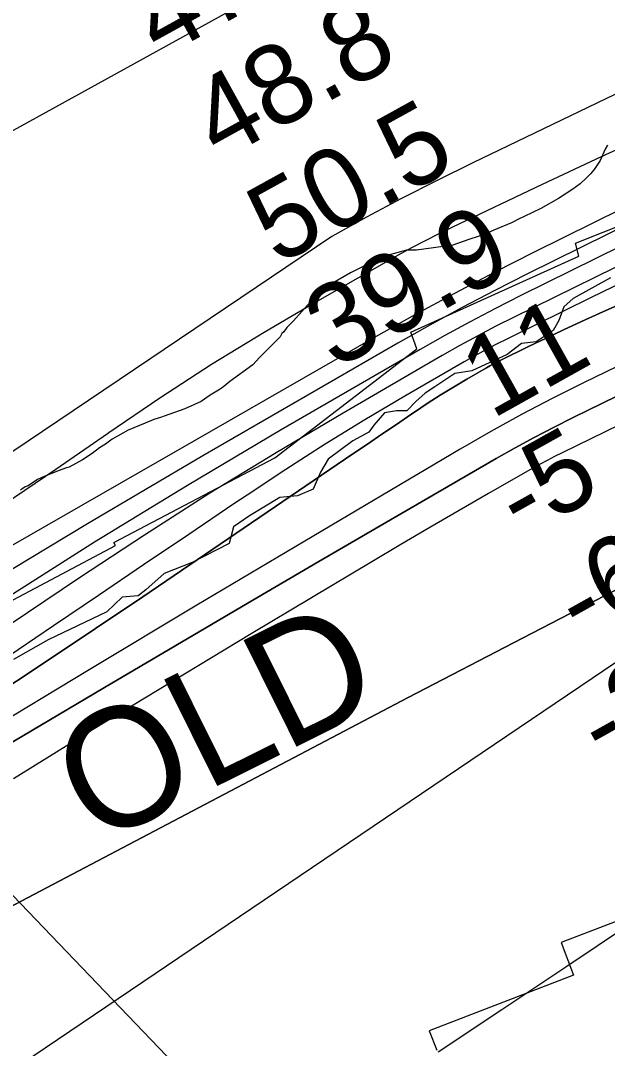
# Model space of a CAD drawing. Extents: x 3177385 to 3215275, y 903885 to 929304.
# Drawn here: x 3183725 to 3184218, y 910634 to 911498 of the extents above; entities that cross this region are included whole.
import ezdxf

# ---------------------------------------------------------------- set-up
doc = ezdxf.new("R2010")
doc.units = 0
for name, color, linetype in [('V-RIVR-EDGE', 7, 'Continuous'), ('V-RIVR-RANG', 7, 'Continuous'), ('V-RRAP-RVMT', 7, 'Continuous'), ('V-RRAP-RVMT-IDEN', 7, 'Continuous'), ('V-SITE-VEGE', 7, 'Continuous'), ('V-TOPO-DPTH', 7, 'Continuous'), ('V-TOPO-MAJR', 7, 'Continuous'), ('V-TOPO-MINR', 7, 'Continuous'), ('V-TOPO-WATR', 7, 'Continuous')]:
    doc.layers.add(name, color=color, linetype=linetype)

msp = doc.modelspace()

# ---------------------------------------------------------------- linework, layer by layer
at = {"layer": 'V-RIVR-EDGE'}
for points in [[(3184221.07, 911282.08), (3184189.62, 911264.61), (3184181.75, 911257.7), (3184177.56, 911246.17), (3184172.92, 911237.86), (3184158.58, 911228.2), (3184146.11, 911226.84), (3184134.08, 911217.64), (3184104.48, 911203.85), (3184090.16, 911201.58)], [(3184090.16, 911201.58), (3184073.5, 911190.54), (3184065.18, 911185.01), (3184057.31, 911178.11), (3184049.9, 911170.27), (3184041.12, 911170.29), (3184030.96, 911168.47), (3184022.16, 911158.33), (3184017.98, 911152.34), (3184004.57, 911144.98), (3183983.75, 911129.79), (3183977.26, 911118.72), (3183971.22, 911104.42), (3183957.81, 911098.91), (3183943.03, 911097.56), (3183917.58, 911081.92), (3183904.17, 911072.72), (3183900.44, 911058.87), (3183869.45, 911042.78), (3183845.87, 911033.6), (3183830.6, 911019.78), (3183824.12, 911014.72), (3183810.72, 911013.83), (3183797.76, 911001.39), (3183748.28, 910977.95), (3183719.14, 910961.4)]]:
    msp.add_lwpolyline(points, dxfattribs=at)
at = {"layer": 'V-RIVR-RANG'}
msp.add_line((3183274.2, 911225.62), (3183980.74, 910489.96), dxfattribs=at)
at = {"layer": 'V-RRAP-RVMT'}
for p, q in [((3184191.63, 911311.06), (3184332.05, 911367.55)), ((3184194.49, 911300.27), (3184191.63, 911311.06)), ((3184053.26, 911236.45), (3184194.49, 911300.27)), ((3184058.23, 911222.29), (3184053.26, 911236.45)), ((3183939.02, 911130.92), (3184058.23, 911222.29)), ((3183803.6, 911059.75), (3183939.02, 911130.92)), ((3183805.07, 911057.02), (3183803.6, 911059.75)), ((3183674.33, 910987.92), (3183805.07, 911057.02)), ((3184300.8, 910770.14), (3184179.43, 910723.56)), ((3184179.43, 910723.56), (3184190.03, 910695.96)), ((3184190.03, 910695.96), (3184068.66, 910649.37)), ((3184068.66, 910649.37), (3184074.96, 910632.97))]:
    msp.add_line(p, q, dxfattribs=at)
at = {"layer": 'V-SITE-VEGE'}
for p, q in [((3184216.41, 911390.06), (3184212.37, 911380.79)), ((3184218.44, 911393.66), (3184216.41, 911390.06)), ((3184212.37, 911380.79), (3184207.29, 911373.05)), ((3184204.23, 911369.43), (3184200.66, 911365.82)), ((3184207.29, 911373.05), (3184204.23, 911369.43)), ((3184195.56, 911361.16), (3184189.44, 911356.49)), ((3184200.66, 911365.82), (3184195.56, 911361.16)), ((3184189.44, 911356.49), (3184177.17, 911348.71)), ((3184177.17, 911348.71), (3184162.34, 911340.39)), ((3184162.34, 911340.39), (3184148.52, 911333.62)), ((3184137.78, 911328.41), (3184122.93, 911322.15)), ((3184144.94, 911332.05), (3184137.78, 911328.41)), ((3184148.52, 911333.62), (3184144.94, 911332.05)), ((3184119.86, 911320.58), (3184110.65, 911316.93)), ((3184122.93, 911322.15), (3184119.86, 911320.58)), ((3184088.63, 911309.58), (3184057.85, 911305.26)), ((3184101.94, 911314.3), (3184088.63, 911309.58)), ((3184110.65, 911316.93), (3184101.94, 911314.3)), ((3184035.29, 911301.51), (3184025.05, 911297.84)), ((3184049.64, 911305.2), (3184035.29, 911301.51)), ((3184057.85, 911305.26), (3184049.64, 911305.2)), ((3184025.05, 911297.84), (3184002.54, 911286.39)), ((3184002.54, 911286.39), (3183983.11, 911274.96)), ((3183983.11, 911274.96), (3183974.43, 911267.71)), ((3183974.43, 911267.71), (3183968.83, 911262.02)), ((3183968.83, 911262.02), (3183961.7, 911253.76)), ((3183961.7, 911253.76), (3183954.56, 911246.01)), ((3183948.96, 911240.32), (3183946.42, 911236.71)), ((3183954.56, 911246.01), (3183948.96, 911240.32)), ((3183943.37, 911232.58), (3183926.03, 911215)), ((3183944.89, 911235.16), (3183943.37, 911232.58)), ((3183946.42, 911236.71), (3183944.89, 911235.16)), ((3183926.03, 911215), (3183920.43, 911208.81)), ((3183920.43, 911208.81), (3183901.02, 911194.81)), ((3183892.85, 911188.59), (3183884.67, 911183.4)), ((3183895.91, 911190.66), (3183892.85, 911188.59)), ((3183901.02, 911194.81), (3183895.91, 911190.66)), ((3183884.67, 911183.4), (3183877.01, 911178.21)), ((3183863.19, 911171.95), (3183845.78, 911165.67)), ((3183877.01, 911178.21), (3183863.19, 911171.95)), ((3183837.07, 911163.04), (3183829.9, 911159.91)), ((3183842.7, 911164.62), (3183837.07, 911163.04)), ((3183845.78, 911165.67), (3183842.7, 911164.62)), ((3183815.57, 911154.16), (3183802.27, 911146.37)), ((3183829.9, 911159.91), (3183815.57, 911154.16)), ((3183802.27, 911146.37), (3183796.66, 911142.22)), ((3183791.54, 911139.11), (3183785.42, 911134.44)), ((3183796.66, 911142.22), (3183791.54, 911139.11)), ((3183777.24, 911129.25), (3183765.99, 911123.01)), ((3183785.42, 911134.44), (3183777.24, 911129.25)), ((3183756.77, 911119.87), (3183752.16, 911117.78)), ((3183763.94, 911122.48), (3183756.77, 911119.87)), ((3183765.99, 911123.01), (3183763.94, 911122.48)), ((3183739.37, 911112.56), (3183731.7, 911107.37)), ((3183744.99, 911115.16), (3183739.37, 911112.56)), ((3183752.16, 911117.78), (3183744.99, 911115.16)), ((3183725.31, 911103.86), (3183725.07, 911103.7)), ((3183726.99, 911104.94), (3183725.31, 911103.86)), ((3183729.14, 911106.33), (3183726.99, 911104.94)), ((3183731.7, 911107.37), (3183729.14, 911106.33))]:
    msp.add_line(p, q, dxfattribs=at)
at = {"layer": 'V-TOPO-DPTH'}
for points in [[(3184959.12, 911628.83), (3184559.24, 911448.89), (3184483.61, 911414.39), (3184408.23, 911379.38), (3184333.21, 911343.58), (3184258.44, 911307.28), (3184140.07, 911249.04), (3184124.74, 911241.31), (3184109.53, 911233.37), (3184094.48, 911225.13), (3184079.54, 911216.67), (3183996.2, 911168.41), (3183940.02, 911135.11), (3183884.3, 911101.08), (3183829.27, 911065.93), (3183774.71, 911030.05), (3183701.64, 910980.94)], [(3185010.94, 911540.97), (3184625.1, 911370.07), (3184546.32, 911334.65), (3184467.81, 911298.65), (3184389.71, 911261.77), (3184311.89, 911224.31), (3184189.62, 911164.61), (3184173.22, 911156.38), (3184156.95, 911147.93), (3184140.86, 911139.13), (3184124.89, 911130.1), (3184036.12, 911078.62), (3183975.9, 911043.6), (3183915.75, 911008.47), (3183855.69, 910973.17), (3183795.7, 910937.77), (3183364.77, 910682.67)], [(3183364.77, 910682.67), (3183795.7, 910937.77), (3183855.69, 910973.17), (3183915.75, 911008.47), (3183975.9, 911043.6), (3184036.12, 911078.62), (3184124.89, 911130.1), (3184140.86, 911139.13), (3184156.95, 911147.93), (3184173.22, 911156.38), (3184189.62, 911164.61), (3184311.89, 911224.31), (3184389.71, 911261.77), (3184467.81, 911298.65), (3184546.32, 911334.65), (3184625.1, 911370.07), (3185010.94, 911540.97)], [(3182613.66, 910009.42), (3183374.91, 910561.12), (3183376.69, 910562.65), (3183380.11, 910565.86), (3183381.75, 910567.55), (3183385.06, 910570.88), (3183386.79, 910572.47), (3183388.56, 910574.01), (3183399.8, 910583.5), (3183402.41, 910585.56), (3183405.1, 910587.51), (3183407.91, 910589.28), (3183410.79, 910590.94), (3183698.78, 910744.26), (3184050.92, 910929.31), (3184146.95, 910979.11), (3184187.23, 910999.97), (3184227.54, 911020.79), (3184267.87, 911041.55), (3184308.22, 911062.28), (3184475.65, 911148.12), (3184575.52, 911199.16), (3184675.47, 911250.05), (3184775.55, 911300.68)], [(3182752.23, 910109.84), (3183374.91, 910561.12), (3183376.69, 910562.65), (3183380.11, 910565.86), (3183381.75, 910567.55), (3183385.06, 910570.88), (3183386.79, 910572.47), (3183388.56, 910574.01), (3183399.8, 910583.5), (3183402.41, 910585.56), (3183405.1, 910587.51), (3183407.91, 910589.28), (3183410.79, 910590.94), (3183698.78, 910744.26), (3184050.92, 910929.31), (3184146.95, 910979.11), (3184187.23, 910999.97), (3184227.54, 911020.79), (3184267.87, 911041.55), (3184308.22, 911062.28), (3184475.65, 911148.12), (3184575.52, 911199.16), (3184675.47, 911250.05), (3184775.55, 911300.68)], [(3184265.65, 911276.1), (3184211.49, 911252.06), (3184196.54, 911245.32), (3184181.64, 911238.46), (3184166.82, 911231.43), (3184152.06, 911224.29), (3184128.73, 911212.84), (3184125.69, 911211.3), (3184122.66, 911209.72), (3184119.67, 911208.09), (3184116.7, 911206.41), (3184100.15, 911196.82), (3184088.99, 911190.19), (3184077.93, 911183.41), (3184067.02, 911176.39), (3184056.22, 911169.21), (3184053.28, 911167.21), (3184041.07, 911158.91), (3184028.87, 911150.62), (3184016.66, 911142.32), (3184004.45, 911134.02), (3183827.97, 911014.1), (3183748.34, 910960.64), (3183668.33, 910907.79)], [(3183668.33, 910907.79), (3183748.34, 910960.64), (3183827.97, 911014.1), (3184004.45, 911134.02), (3184016.66, 911142.32), (3184028.87, 911150.62), (3184041.07, 911158.91), (3184053.28, 911167.21), (3184056.22, 911169.21), (3184067.02, 911176.39), (3184077.93, 911183.41), (3184088.99, 911190.19), (3184100.15, 911196.82), (3184116.7, 911206.41), (3184119.67, 911208.09), (3184122.66, 911209.72), (3184125.69, 911211.3), (3184128.73, 911212.84), (3184152.06, 911224.29), (3184166.82, 911231.43), (3184181.64, 911238.46), (3184196.54, 911245.32), (3184211.49, 911252.06), (3184265.65, 911276.1)], [(3184235.85, 910965.83), (3183511.28, 910476.54)], [(3184235.85, 910965.83), (3183511.28, 910476.54)], [(3184076.07, 910631.58), (3184129.77, 910667.28), (3184183.41, 910703.07), (3184237.01, 910738.92)], [(3184076.07, 910631.58), (3184129.77, 910667.28), (3184183.41, 910703.07), (3184237.01, 910738.92)]]:
    msp.add_lwpolyline(points, dxfattribs=at)
at = {"layer": 'V-TOPO-MAJR'}
msp.add_lwpolyline([(3184674.22, 911559.76), (3184156.98, 911303.54), (3184123.26, 911286.45), (3184089.76, 911268.96), (3184056.59, 911250.86), (3184023.63, 911232.35), (3183717.07, 911056.53), (3183645.62, 911014.91), (3183574.55, 910972.66), (3183504.06, 910929.46), (3183433.94, 910885.63), (3183330.87, 910820.23), (3183312.63, 910808.54), (3183294.46, 910796.75), (3183276.4, 910784.79), (3183258.4, 910772.73), (3182636, 910221.52)], dxfattribs=at)
at = {"layer": 'V-TOPO-MINR'}
for points in [[(3184745.01, 911681.01), (3184664.63, 911644.77), (3184584.48, 911608.06), (3184504.65, 911570.64), (3184425.05, 911532.74), (3184105.18, 911378.73), (3184075.22, 911363.93), (3184045.48, 911348.73), (3184016.06, 911332.92), (3183986.84, 911316.71), (3183398.74, 910920.7), (3183382.76, 910908.54), (3183366.39, 910896.86), (3183362.26, 910894.06), (3183347.61, 910884.25), (3183332.87, 910874.56), (3183318.01, 910865.06), (3183303.07, 910855.69), (3183288.11, 910846.36), (3183273.2, 910836.94), (3183258.36, 910827.41), (3183243.57, 910817.8), (3182487.62, 910217.22), (3182486.51, 910216.5)], [(3183126.4, 911092.4), (3183126.96, 911092.53), (3183136.76, 911095.46), (3183146.28, 911099.21), (3183155.61, 911103.5), (3183250.82, 911152.33), (3183307.47, 911181.72), (3183363.95, 911211.44), (3183420.15, 911241.67), (3183476.17, 911272.24), (3183921.54, 911517.91), (3183932.74, 911524.68), (3183943.52, 911532.01), (3183953.7, 911540.16), (3183963.46, 911548.88), (3183967.57, 911552.85), (3183978.25, 911564.55), (3183987.84, 911576.96), (3183995.83, 911590.48), (3184002.74, 911604.72), (3184011.97, 911627.21), (3184024.27, 911652.12), (3184025.01, 911653.33)], [(3184959.12, 911628.83), (3184559.24, 911448.89), (3184483.61, 911414.39), (3184408.23, 911379.38), (3184333.21, 911343.58), (3184258.44, 911307.28), (3184140.07, 911249.04), (3184124.74, 911241.31), (3184109.53, 911233.37), (3184094.48, 911225.13), (3184079.54, 911216.67), (3183996.2, 911168.41), (3183940.02, 911135.11), (3183884.3, 911101.08), (3183829.27, 911065.93), (3183774.71, 911030.05), (3183701.64, 910980.94)], [(3184833.09, 911551.64), (3184383.85, 911349.68), (3184338.83, 911329.16), (3184293.95, 911308.34), (3184249.28, 911287.06), (3184204.76, 911265.48), (3184134.41, 911230.93), (3184125.22, 911226.3), (3184116.1, 911221.54), (3184107.08, 911216.6), (3184098.12, 911211.54), (3184048.16, 911182.61), (3184014.5, 911162.64), (3183981.12, 911142.21), (3183948.18, 911121.08), (3183915.52, 911099.5), (3183904.52, 911092.06), (3183866.58, 911066.42), (3183828.63, 911040.77), (3183790.69, 911015.14), (3183752.74, 910989.5), (3183678.29, 910939.23)], [(3184612.19, 911558.41), (3184362.78, 911450.75), (3184312.72, 911428.83), (3184262.83, 911406.55), (3184213.18, 911383.74), (3184163.69, 911360.57), (3184088.11, 911324.69), (3184076.59, 911319.07), (3184065.17, 911313.28), (3184053.87, 911307.24), (3184042.67, 911301.04), (3183974.68, 911262.41), (3183929.94, 911236.15), (3183885.7, 911209.09), (3183842.23, 911180.8), (3183799.27, 911151.71), (3183798.19, 911150.96), (3183754.92, 911121.12), (3183711.44, 911091.59)], [(3185010.94, 911540.97), (3184625.1, 911370.07), (3184546.32, 911334.65), (3184467.81, 911298.65), (3184389.71, 911261.77), (3184311.89, 911224.31), (3184189.62, 911164.61), (3184173.22, 911156.38), (3184156.95, 911147.93), (3184140.86, 911139.13), (3184124.89, 911130.1), (3184036.12, 911078.62), (3183975.9, 911043.6), (3183915.75, 911008.47), (3183855.69, 910973.17), (3183795.7, 910937.77), (3183364.77, 910682.67)], [(3184643.12, 911526.61), (3184566.09, 911489.79), (3184489.34, 911452.39), (3184151.35, 911285.35), (3184123.77, 911271.38), (3184096.37, 911257.07), (3184069.25, 911242.22), (3184042.32, 911227.02), (3183878.5, 911132.47), (3183781.5, 911075.42), (3183685.15, 911017.31), (3183589.77, 910957.63), (3183495.03, 910896.9), (3183320.88, 910783.23), (3183313.73, 910778.51), (3183306.6, 910773.76), (3183299.51, 910768.94), (3183292.45, 910764.08), (3182709.2, 910259.2)], [(3184631.37, 911501.24), (3184524.85, 911451.78), (3184418.88, 911401.17), (3184313.27, 911349.8), (3184145.72, 911267.18), (3184124.26, 911256.34), (3184102.96, 911245.2), (3184081.88, 911233.65), (3184060.96, 911221.81), (3183944.22, 911154.2), (3183865.51, 911107.6), (3183787.41, 911060), (3183710.25, 911010.91)], [(3184730.38, 911444.92), (3184637.02, 911403.55), (3184544.34, 911360.7), (3184452.11, 911316.86), (3184199, 911194.07), (3184172.53, 911180.82), (3184146.28, 911167.14), (3184120.38, 911152.81), (3184094.72, 911138.06), (3183964.11, 911060.8), (3183873.43, 911006.9), (3183782.9, 910952.74), (3183692.61, 910898.21), (3183602.47, 910843.41), (3183369.8, 910701.31), (3183360.43, 910695.48), (3183351.13, 910689.56), (3183341.92, 910683.49), (3182687.28, 910141.97)], [(3184730.8, 911377.42), (3184664.36, 911350.24), (3184598.08, 911322.67), (3184532.04, 911294.53), (3184466.16, 911266.01), (3184351.42, 911215.72), (3184320.46, 911201.92), (3184289.63, 911187.85), (3184258.98, 911173.38), (3184228.45, 911158.65), (3184180.29, 911135.03), (3184173.97, 911131.85), (3184167.68, 911128.6), (3184161.47, 911125.23), (3184155.29, 911121.78), (3184118.36, 911100.7), (3184093.79, 911086.58), (3184069.27, 911072.36), (3184044.85, 911057.99), (3184020.48, 911043.53), (3183919.09, 910982.91), (3183852.26, 910942.66), (3183785.61, 910902.1), (3183719.24, 910861.1)], [(3184775.55, 911300.68), (3184675.47, 911250.05), (3184575.52, 911199.16), (3184475.65, 911148.12), (3184308.22, 911062.28), (3184267.87, 911041.55), (3184227.54, 911020.79), (3184187.23, 910999.97), (3184146.95, 910979.11), (3184050.92, 910929.31), (3183698.78, 910744.26), (3183410.79, 910590.94), (3183407.91, 910589.28), (3183405.1, 910587.51), (3183402.41, 910585.56), (3183399.8, 910583.5), (3183388.56, 910574.01), (3183386.79, 910572.47), (3183385.06, 910570.88), (3183381.75, 910567.55), (3183380.11, 910565.86), (3183376.69, 910562.65), (3183374.91, 910561.12), (3182613.66, 910009.42)], [(3184235.85, 910965.83), (3183511.28, 910476.54)], [(3184235.85, 910965.83), (3183511.28, 910476.54)], [(3184076.07, 910631.58), (3184129.77, 910667.28), (3184183.41, 910703.07), (3184237.01, 910738.92)], [(3184076.07, 910631.58), (3184129.77, 910667.28), (3184183.41, 910703.07), (3184237.01, 910738.92)]]:
    msp.add_lwpolyline(points, dxfattribs=at)
at = {"layer": 'V-TOPO-WATR'}
msp.add_lwpolyline([(3184265.65, 911276.1), (3184211.49, 911252.06), (3184196.54, 911245.32), (3184181.64, 911238.46), (3184166.82, 911231.43), (3184152.06, 911224.29), (3184128.73, 911212.84), (3184125.69, 911211.3), (3184122.66, 911209.72), (3184119.67, 911208.09), (3184116.7, 911206.41), (3184100.15, 911196.82), (3184088.99, 911190.19), (3184077.93, 911183.41), (3184067.02, 911176.39), (3184056.22, 911169.21), (3184053.28, 911167.21), (3184041.07, 911158.91), (3184028.87, 911150.62), (3184016.66, 911142.32), (3184004.45, 911134.02), (3183827.97, 911014.1), (3183748.34, 910960.64), (3183668.33, 910907.79)], dxfattribs=at)

# ---------------------------------------------------------------- texts
at = {"layer": 'V-RIVR-RANG'}
for s, rotation, p in [('47.6', 28.88833, (3183842.43, 911466.02)), ('48.8', 28.88833, (3183892.58, 911379.48)), ('50.5', 28.88833, (3183941.11, 911292.05)), ('39.9', 28.88833, (3183989.41, 911204.49)), ('11', 29.19167, (3184121.08, 911162.78)), ('-5', 29.19167, (3184146.35, 911062.35)), ('-6', 29.19167, (3184196.26, 910975.69)), ('-25', 29.19167, (3184215.32, 910871.78))]:
    msp.add_text(s, height=67, rotation=rotation, dxfattribs=at).set_placement(p)
at = {"layer": 'V-RRAP-RVMT-IDEN'}
msp.add_text('OLD', height=100, rotation=26.42923, dxfattribs=at).set_placement((3183787.58, 910803.77))

doc.saveas('drawing.dxf')
